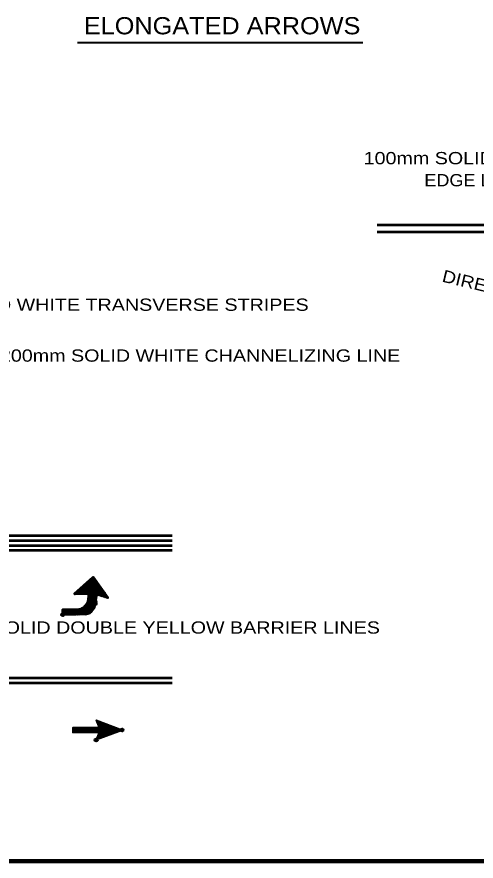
# Model space of a CAD drawing. Extents: x -96 to 617, y -65 to 388.
# Drawn here: x 137.3 to 230.8, y -55.4 to 116.7 of the extents above; entities that cross this region are included whole.
import ezdxf
from ezdxf.enums import TextEntityAlignment as Align

# ---------------------------------------------------------------- set-up
doc = ezdxf.new("R2010")
doc.units = 0
doc.header["$PDMODE"] = 32
doc.header["$PDSIZE"] = 0.5
doc.layers.add('1', color=7, linetype='Continuous', lineweight=53)

msp = doc.modelspace()

# ---------------------------------------------------------------- linework, layer by layer
at = {"layer": '1', "lineweight": 40}
msp.add_line((149.585, 111.47), (207.777, 111.47), dxfattribs=at)
at = {"layer": '1'}
for p, q in [((210.689, 74.258), (414.688, 74.258)), ((235.189, 72.758), (210.689, 72.758)), ((-19.121, 10.942), (168.879, 10.942)), ((-19.121, 9.942), (168.879, 9.942)), ((-19.121, 8.942), (168.879, 8.942)), ((112.879, 7.942), (168.879, 7.942)), ((151.959, 1.732), (155.301, -1.609)), ((151.959, 1.732), (155.098, -1.508)), ((152.061, 1.833), (155.503, -1.609)), ((152.162, 1.934), (155.706, -1.711)), ((152.263, 2.036), (155.199, -0.799)), ((152.263, 1.934), (155.503, -1.407)), ((152.364, 2.137), (154.794, -0.293)), ((152.466, 2.137), (154.389, 0.213)), ((152.567, 2.339), (153.579, 1.327)), ((152.567, 2.238), (153.984, 0.821)), ((152.668, 2.339), (153.174, 1.833)), ((150.036, 0.011), (150.947, -0.901)), ((150.137, 0.112), (151.251, -0.901)), ((150.137, 0.112), (151.048, -0.901)), ((150.238, 0.213), (151.352, -0.901)), ((150.339, 0.314), (151.554, -0.901)), ((150.441, 0.416), (151.757, -0.901)), ((150.441, 0.314), (151.656, -0.901)), ((150.542, 0.517), (151.959, -0.901)), ((150.643, 0.517), (153.276, -2.116)), ((150.744, 0.719), (153.377, -1.913)), ((150.744, 0.618), (153.377, -2.014)), ((150.846, 0.719), (153.377, -1.711)), ((150.947, 0.821), (153.377, -1.609)), ((151.048, 0.922), (153.377, -1.407)), ((151.048, 0.922), (153.377, -1.508)), ((151.149, 1.023), (153.478, -1.306)), ((151.251, 1.124), (153.478, -1.103)), ((151.352, 1.226), (153.681, -1.103)), ((151.352, 1.124), (153.478, -1.002)), ((151.453, 1.327), (153.883, -1.103)), ((151.554, 1.327), (154.086, -1.204)), ((151.656, 1.529), (154.491, -1.306)), ((151.656, 1.428), (154.288, -1.204)), ((151.757, 1.529), (154.693, -1.407)), ((151.858, 1.631), (154.896, -1.407)), ((149.023, -0.901), (149.124, -0.901)), ((149.124, -0.799), (149.226, -0.901)), ((149.226, -0.698), (149.327, -0.901)), ((149.327, -0.597), (149.631, -0.901)), ((149.327, -0.698), (149.529, -0.901)), ((149.428, -0.496), (149.833, -0.901)), ((149.529, -0.496), (149.934, -0.901)), ((149.631, -0.293), (150.238, -0.901)), ((149.631, -0.394), (150.036, -0.901)), ((149.732, -0.293), (150.339, -0.901)), ((149.833, -0.192), (150.542, -0.901)), ((149.934, -0.091), (150.846, -0.901)), ((149.934, -0.091), (150.643, -0.901)), ((151.858, -1.407), (153.174, -2.723)), ((151.858, -1.711), (153.174, -3.027)), ((151.959, -0.901), (153.276, -2.217)), ((151.959, -1.002), (153.276, -2.419)), ((151.959, -1.204), (153.276, -2.521)), ((151.959, -1.306), (153.174, -2.521)), ((151.149, -3.432), (152.364, -4.647)), ((151.251, -3.331), (152.466, -4.546)), ((151.352, -3.229), (152.567, -4.444)), ((151.352, -3.229), (152.466, -4.444)), ((151.453, -3.027), (152.668, -4.242)), ((151.453, -3.128), (152.668, -4.343)), ((151.554, -2.824), (152.871, -4.039)), ((151.554, -2.926), (152.769, -4.141)), ((151.656, -2.622), (152.972, -3.938)), ((151.656, -2.723), (152.871, -4.039)), ((151.757, -2.217), (153.073, -3.533)), ((151.757, -2.318), (153.073, -3.634)), ((151.757, -2.419), (153.073, -3.736)), ((151.757, -2.521), (152.972, -3.837)), ((151.858, -1.812), (153.174, -3.128)), ((151.858, -1.913), (153.174, -3.229)), ((151.858, -2.014), (153.174, -3.432)), ((153.174, -2.521), (153.276, -2.622)), ((153.174, -2.723), (153.276, -2.723)), ((146.593, -4.141), (147.606, -5.153)), ((146.593, -4.242), (147.504, -5.153)), ((146.593, -4.444), (147.302, -5.153)), ((146.593, -4.546), (147.201, -5.153)), ((146.593, -4.748), (146.998, -5.153)), ((146.593, -4.849), (146.897, -5.153)), ((146.593, -5.052), (146.694, -5.153)), ((146.694, -4.141), (147.707, -5.153)), ((146.897, -4.141), (147.909, -5.153)), ((146.998, -4.141), (148.011, -5.153)), ((147.201, -4.141), (148.213, -5.153)), ((147.302, -4.141), (148.314, -5.153)), ((147.403, -4.141), (148.416, -5.153)), ((147.606, -4.141), (148.618, -5.153)), ((147.707, -4.141), (148.719, -5.153)), ((147.909, -4.141), (148.922, -5.153)), ((148.011, -4.141), (149.023, -5.153)), ((148.213, -4.141), (149.124, -5.153)), ((148.314, -4.141), (149.327, -5.153)), ((148.416, -4.141), (149.428, -5.153)), ((148.618, -4.141), (149.631, -5.153)), ((148.719, -4.141), (149.732, -5.153)), ((148.922, -4.141), (149.833, -5.153)), ((149.023, -4.141), (150.036, -5.153)), ((149.124, -4.141), (150.137, -5.153)), ((149.327, -4.141), (150.238, -5.052)), ((149.428, -4.141), (150.441, -5.052)), ((149.631, -4.141), (150.542, -5.052)), ((149.732, -4.141), (150.643, -5.052)), ((149.833, -4.141), (150.846, -5.052)), ((149.934, -4.039), (150.947, -5.052)), ((150.036, -4.039), (151.048, -5.052)), ((150.238, -4.039), (151.251, -5.052)), ((150.339, -3.938), (151.352, -5.052)), ((150.441, -3.938), (151.554, -4.951)), ((150.441, -3.938), (151.453, -5.052)), ((150.542, -3.837), (151.656, -4.951)), ((150.643, -3.837), (151.757, -4.951)), ((150.744, -3.736), (151.858, -4.849)), ((150.846, -3.634), (151.959, -4.849)), ((150.947, -3.634), (152.061, -4.748)), ((151.048, -3.533), (152.263, -4.647)), ((151.048, -3.533), (152.162, -4.748)), ((132.879, -18.058), (168.879, -18.058)), ((132.879, -19.058), (168.879, -19.058))]:
    msp.add_line(p, q, dxfattribs=at)
at = {"layer": '1', "lineweight": 35}
for p, q in [((153.414, -26.765), (156.35, -29.6)), ((153.515, -26.967), (156.249, -29.701)), ((153.616, -26.765), (156.451, -29.6)), ((153.616, -27.17), (156.147, -29.701)), ((153.717, -27.473), (156.046, -29.701)), ((153.819, -26.866), (156.552, -29.498)), ((154.021, -26.866), (156.654, -29.498)), ((154.325, -26.967), (156.755, -29.498)), ((154.527, -27.068), (156.856, -29.397)), ((154.73, -27.17), (156.957, -29.397)), ((154.932, -27.271), (157.059, -29.296)), ((155.236, -27.372), (157.16, -29.296)), ((155.439, -27.473), (157.261, -29.296)), ((155.641, -27.473), (157.362, -29.195)), ((148.655, -28.182), (154.021, -28.182)), ((148.655, -28.283), (149.566, -29.195)), ((148.655, -28.385), (149.465, -29.195)), ((148.655, -28.486), (149.364, -29.195)), ((148.655, -28.688), (149.161, -29.195)), ((148.655, -28.79), (149.06, -29.195)), ((148.655, -28.992), (148.857, -29.195)), ((148.655, -29.093), (148.756, -29.195)), ((148.756, -28.182), (149.769, -29.195)), ((148.857, -28.182), (149.87, -29.195)), ((149.06, -28.182), (150.072, -29.195)), ((149.161, -28.182), (150.174, -29.195)), ((149.364, -28.182), (150.376, -29.195)), ((149.465, -28.182), (150.477, -29.195)), ((149.566, -28.182), (150.579, -29.195)), ((149.769, -28.182), (150.781, -29.195)), ((149.87, -28.182), (150.882, -29.195)), ((150.072, -28.182), (151.085, -29.195)), ((150.174, -28.182), (151.186, -29.195)), ((150.275, -28.182), (151.287, -29.195)), ((150.477, -28.182), (151.49, -29.195)), ((150.579, -28.182), (151.591, -29.195)), ((150.781, -28.182), (151.794, -29.195)), ((150.882, -28.182), (151.895, -29.195)), ((151.085, -28.182), (152.097, -29.195)), ((151.186, -28.182), (152.199, -29.195)), ((151.287, -28.182), (152.3, -29.195)), ((151.49, -28.182), (152.502, -29.195)), ((151.591, -28.182), (152.604, -29.195)), ((151.794, -28.182), (152.806, -29.195)), ((151.895, -28.182), (152.907, -29.195)), ((151.996, -28.182), (153.009, -29.195)), ((152.199, -28.182), (153.211, -29.195)), ((152.3, -28.182), (153.312, -29.195)), ((152.502, -28.182), (153.515, -29.195)), ((152.604, -28.182), (153.616, -29.195)), ((152.705, -28.182), (153.717, -29.195)), ((152.907, -28.182), (153.92, -29.195)), ((153.009, -28.182), (154.932, -30.106)), ((153.211, -28.182), (155.135, -30.106)), ((153.312, -28.182), (155.236, -30.005)), ((153.515, -28.182), (155.337, -30.005)), ((153.616, -28.182), (155.439, -30.005)), ((153.717, -28.182), (155.54, -29.903)), ((153.819, -27.676), (155.945, -29.802)), ((153.92, -27.878), (155.844, -29.802)), ((153.92, -28.182), (155.641, -29.903)), ((154.021, -28.182), (155.742, -29.802)), ((155.945, -27.575), (157.464, -29.195)), ((156.147, -27.676), (157.565, -29.093)), ((156.35, -27.777), (157.666, -29.093)), ((156.552, -27.878), (157.767, -29.093)), ((156.856, -27.98), (157.869, -28.992)), ((157.059, -28.081), (157.97, -28.992)), ((157.261, -28.081), (158.071, -28.992)), ((157.464, -28.182), (158.172, -28.891)), ((157.767, -28.283), (158.274, -28.891)), ((157.97, -28.385), (158.375, -28.79)), ((158.172, -28.486), (158.476, -28.79)), ((158.375, -28.587), (158.577, -28.79)), ((153.414, -30.612), (153.515, -30.713)), ((153.515, -30.41), (153.717, -30.612)), ((153.515, -30.511), (153.616, -30.612)), ((153.616, -30.106), (154.021, -30.511)), ((153.616, -30.207), (153.92, -30.511)), ((153.616, -30.308), (153.819, -30.511)), ((153.717, -29.903), (154.224, -30.41)), ((153.717, -30.005), (154.122, -30.41)), ((153.819, -29.6), (154.527, -30.308)), ((153.819, -29.701), (154.426, -30.308)), ((153.819, -29.802), (154.325, -30.308)), ((153.92, -29.397), (154.73, -30.207)), ((153.92, -29.498), (154.629, -30.207)), ((154.021, -29.296), (154.831, -30.207))]:
    msp.add_line(p, q, dxfattribs=at)
at = {"layer": '1', "lineweight": 158}
msp.add_line((611.853, -55.407), (-47.814, -55.407), dxfattribs=at)
at = {"layer": '1'}
for points in [[(151.757, -2.521), (151.959, -0.901), (149.023, -0.901), (152.769, 2.441), (152.769, 2.339)], [(152.769, 2.441), (155.807, -1.711), (153.478, -1.002), (153.174, -3.128)], [(151.858, -1.508), (153.174, -2.824), (153.174, -2.926)], [(151.251, -5.052), (149.124, -5.153), (146.593, -5.153), (146.593, -4.141), (149.124, -4.141)]]:
    msp.add_lwpolyline(points, dxfattribs=at)
at = {"layer": '1', "lineweight": 35}
msp.add_lwpolyline([(158.78, -28.688), (153.414, -30.713), (154.021, -29.195), (148.655, -29.195), (148.655, -28.182), (154.021, -28.182), (153.414, -26.663)], close=True, dxfattribs=at)
msp.add_lwpolyline([(154.021, -29.195), (148.655, -29.195), (148.655, -28.182)], dxfattribs=at)
at = {"layer": '1'}
for centre, radius, start, end in [((149.366, -1.585), 2.567, 264.58762, 338.62739), ((151.019, -2.879), 2.185, 276.08048, 9.44985)]:
    msp.add_arc(centre, radius, start, end, dxfattribs=at)
for p in [(151.959, -0.901), (153.174, -2.521), (153.174, -2.723), (153.174, -2.926), (153.174, -3.027), (146.593, -5.153), (158.679, -28.688), (153.414, -30.713)]:
    msp.add_point(p, dxfattribs=at)

# ---------------------------------------------------------------- texts
at = {"layer": '1', "width": 1.1}
msp.add_text('ELONGATED ARROWS', height=3.5, dxfattribs=at).set_placement((150.899, 113.112))
at = {"layer": '1'}
for s, width, p in [('100mm SOLID YELLOW', 1.2, (230.091, 86.626)), ('EDGE LINE', 1.1, (230.091, 82.126)), ('300mm SOLID WHITE TRANSVERSE STRIPES', 1.2, (153.139, 56.752)), ('150mm TO 200mm SOLID WHITE CHANNELIZING LINE', 1.2, (164.003, 46.387)), ('100mm SOLID DOUBLE YELLOW BARRIER LINES', 1.2, (164.415, -9.047))]:
    msp.add_text(s, height=2.5, dxfattribs=dict(at, width=width)).set_placement(p, align=Align.CENTER)
at = {"layer": '1', "width": 1.15}
msp.add_text('DIRECTION OF TRAFFIC', height=2.5, rotation=346.523, dxfattribs=at).set_placement((245.54, 57.496), align=Align.CENTER)

doc.saveas('drawing.dxf')
